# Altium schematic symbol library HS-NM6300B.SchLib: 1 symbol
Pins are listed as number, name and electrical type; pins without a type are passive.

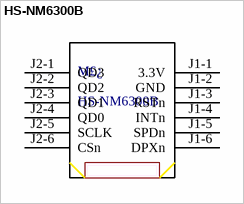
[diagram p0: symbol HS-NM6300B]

## HS-NM6300B
designator M£¿
footprint PCBComponent_1
pins: J1-1 3.3V, J1-2 GND, J1-3 RSTn, J1-4 INTn, J1-5 SPDn, J1-6 DPXn, J2-1 QD3, J2-2 QD2, J2-3 QD1, J2-4 QD0, J2-5 SCLK, J2-6 CSn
